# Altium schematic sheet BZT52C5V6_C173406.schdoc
size 127 x 101 mm
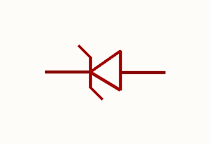
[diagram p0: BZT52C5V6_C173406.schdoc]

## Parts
D?  bzt52c5v6_c173406  [SOD-123_L2.8-W1.8-LS3.7-RD]  (value not drawn)

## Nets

Not connected (* = marked no-connect by the designer): D? 1 2

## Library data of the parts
D? = bzt52c5v6_c173406: 二极管配置:1个独立式;稳压值(标称值):5.6V;稳压值(范围):5.32V~5.88V;耗散功率(Pd):500mW;; Manufacturer: MDD(辰达半导体); AddInBom: yes; ModelId: 7884390a25fb4c08947731ebfba7e3f8; ModelTransform: 144.8816,62.992,0,0,0,0,0,0,0; Diode Configuration: 1个独立式; Zener Voltage(Nom): 5.6V; Reverse Leakage Current (Ir): 1uA@2.5V; Pd - Power Dissipation: 500mW; Impedance(Zzt): 80Ω; Tolerance: ±5%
